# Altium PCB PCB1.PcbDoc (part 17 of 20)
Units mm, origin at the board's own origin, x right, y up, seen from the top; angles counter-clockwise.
Board outline 294.51 x 138.18 mm, 12 copper layers (Top Layer 1 _Signal, L2_GND, L3_Signals, L4_GND, L5_POWER, L6_Signals, L7_GND, L8_Signals, L9_GND, L10_POWER, L11_GND, Bottom Layer_Signals), stack 1.788 mm thick; 1254 components, 836 nets, 5699 pads, 2073 vias.
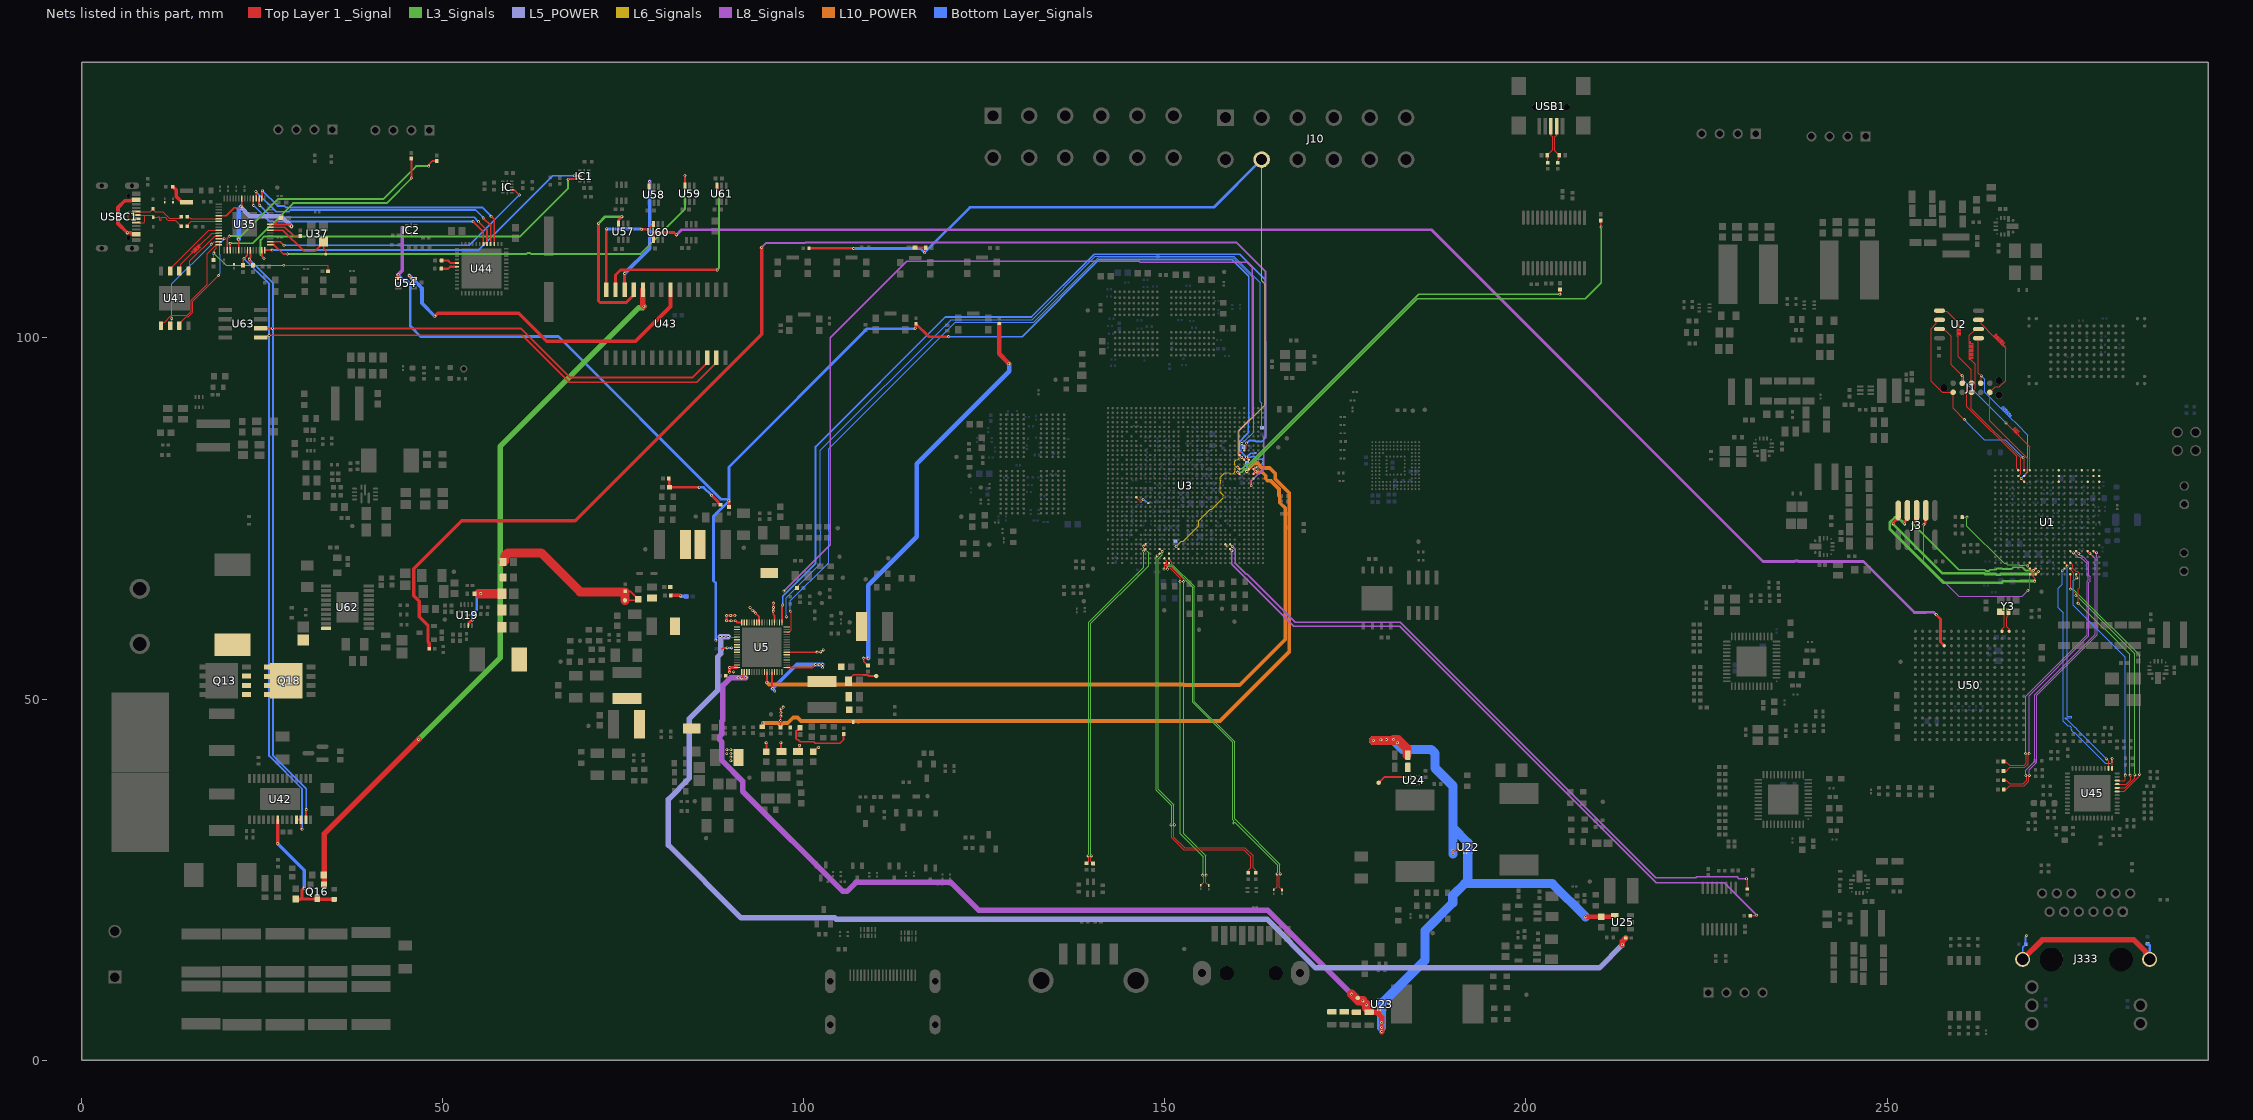
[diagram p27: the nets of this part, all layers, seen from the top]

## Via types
v1: diameter 0.4, hole 0.2, Top Layer 1 _Signal to Bottom Layer_Signals, 2009 vias
v2: diameter 0.508, hole 0.254, Top Layer 1 _Signal to Bottom Layer_Signals, 36 vias
v3: diameter 0.5, hole 0.2, Top Layer 1 _Signal to Bottom Layer_Signals, 12 vias
v4: diameter 1.27, hole 0.711, Top Layer 1 _Signal to Bottom Layer_Signals, 6 vias
v5: diameter 0.3, hole 0.2, Top Layer 1 _Signal to Bottom Layer_Signals, 5 vias
v6: diameter 0.254, hole 0.2, Top Layer 1 _Signal to Bottom Layer_Signals, 3 vias
v7: diameter 0.305, hole 0.2, Top Layer 1 _Signal to Bottom Layer_Signals, 1 vias
v8: diameter 0.254, hole 0.152, Top Layer 1 _Signal to Bottom Layer_Signals, 1 vias

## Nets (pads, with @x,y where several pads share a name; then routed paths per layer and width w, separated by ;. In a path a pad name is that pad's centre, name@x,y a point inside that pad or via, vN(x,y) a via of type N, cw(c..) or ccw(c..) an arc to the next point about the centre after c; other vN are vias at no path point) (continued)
PLDO5: C178.2 C612.1 U3.Y7 U5.65 | length 5
  Top Layer 1 _Signal w0.152: C178.2@96.773,46.044 96.776,46.041 96.788,46.041 96.796,46.049 v1(96.796,47.027) 96.816,47.047 96.816,47.608 v1(96.836,47.627) 96.831,47.632 96.831,48.103 v1(96.826,48.108) 96.838,48.121 96.838,48.622 v1(96.85,48.634) 96.885,48.634 97.128,48.877 v1(97.163,48.877) ; U3.Y7@146.029,77.928 146.356,77.601 v1(146.998,77.601)
  Bottom Layer_Signals w0.152: v1(146.998,77.601) 147.045,77.554 147.254,77.554 147.598,77.21 147.644,77.21 C612.1@147.699,77.155
PMIC_EXT_EN_OUT: R127.2 U5.39 | length 176.9
  Top Layer 1 _Signal w0.127: v1(88.462,58.655) v1(88.943,58.655) v1(89.542,58.655) 89.615,58.655 89.7,58.57 U5.39@90.754,58.57
  Top Layer 1 _Signal w0.762: v1(213.356,15.98) 213.356,16.454 R127.2@213.819,16.917
  L5_POWER w0.762: v1(89.542,58.655) v1(88.943,58.655) v1(88.462,58.655) 88.484,58.633 88.484,56.237 88.11,55.863 88.11,51.227 84.172,47.289 84.172,39.032 81.249,36.109 81.249,29.779 91.337,19.69 104.322,19.69 104.485,19.528 164.134,19.528 170.883,12.779 210.156,12.779 v1(213.356,15.98)
PMIC_FB6: C55.2 R32.1 R33.2 | length 9.4
  Top Layer 1 _Signal w0.381: C55.2@81.315,80.539 81.38,80.474 81.38,79.456 81.377,79.453 R32.1@81.377,79.316 81.379,79.314 85.517,79.314 v1(85.519,79.312) ; v1(87.242,78.219) 88.159,77.302 88.159,77.17 88.414,76.916 R33.2@88.457,76.916
  Bottom Layer_Signals w0.381: v1(85.519,79.312) 86.111,79.312 87.201,78.222 87.239,78.222 v1(87.242,78.219)
PMIC_FB9: C69.2 R35.1 R37.2 U5.66 | length 9.6
  Top Layer 1 _Signal w0.254: R35.1@99.502,46.036 99.502,46.011 99.163,45.672 99.064,45.672 98.941,45.549 98.941,44.534 99.11,44.365 99.226,44.365 99.501,44.091 101.376,44.091 101.585,43.882 105.013,43.882 105.524,44.393 C69.2@105.524,45.164
PMIC_INT_L: R41.1 U3.M30 U5.19 | length 128.7
  Top Layer 1 _Signal w0.203: v1(160.65,83.47) 160.65,83.463 160.979,83.134 U3.M30@160.979,83.128
  L8_Signals w0.203: v1(97.243,64.951) 103.641,71.349 103.641,99.994 114.254,110.607 146.42,110.607 146.523,110.503 161.392,110.503 162.077,109.819 162.077,88.963 161.64,88.526 161.64,88.517 161.414,88.291 161.404,88.291 160.167,87.054 160.167,86.34 160.173,86.335 160.173,86.015 160.167,86.01 160.167,83.952 v1(160.65,83.47)
PMIC_PWR_CTRL1: U3.R32 U5.62 | length 102.1
  Top Layer 1 _Signal w0.254: v1(94.899,52.293) U5.62@94.899,53.725 ; U3.R32@162.279,81.178 162.279,81.188 162.605,81.513 v1(162.605,81.523)
  L10_POWER w0.508: v1(94.899,52.293) 95.182,52.01 152.63,52.01 152.703,51.937 160.358,51.937 166.654,58.233 166.654,76.448 165.911,77.191 165.911,78.046 165.8,78.157 165.8,79.091 164.688,80.203 164.276,80.203 163.961,80.518 163.961,80.929 163.5,81.391 162.737,81.391 v1(162.605,81.523)
PMIC_PWR_CTRL2: R3.1 R20.2 U5.61 | length 110
  Top Layer 1 _Signal w0.381: R20.2@94.227,46.142 94.336,46.251 94.336,46.675 v1(94.34,46.679)
  L10_POWER w0.508: v1(94.34,46.679) 96.384,46.679 96.573,46.49 97.019,46.49 97.208,46.679 97.793,46.679 98.556,47.442 99.147,47.442 99.625,46.963 136.656,46.963 157.625,46.963 167.246,56.584 167.246,78.481 165.307,80.421 165.307,81.185 164.509,81.983 163.43,81.983 163.133,82.28 163.133,82.366 162.817,82.681 162.372,82.681 161.327,81.636 v1(161.327,81.503)
  Bottom Layer_Signals w0.254: v1(161.327,81.503) 161.353,81.529 161.353,82.667 R3.1@161.379,82.693
PMIC_SPI_CLK: R24.2 U5.17 | length 118.8
  Bottom Layer_Signals w0.132: v1(97.596,61.381) 97.596,64.05 102.264,68.719 102.264,72.745 102.367,72.848 102.367,73.137 102.264,73.24 102.264,84.422 120.392,102.55 131.614,102.55 140.37,111.306 159.551,111.306 163.191,107.666 163.191,91.189 163.437,90.943 R24.2@163.437,87.578
PMIC_SPI_CS: U3.K30 U5.18 | length 127.2
  Top Layer 1 _Signal w0.127: U3.K30@160.979,84.428 161.304,84.753 v1(161.304,85.426)
  Top Layer 1 _Signal w0.254: U5.18@96.999,60.615 96.999,62.88 97.096,62.977 v1(97.096,63.017)
  Bottom Layer_Signals w0.254: v1(97.096,63.017) 97.096,64.253 97.383,64.54 97.413,64.54 97.654,64.781 97.654,64.811 101.642,68.799 101.642,72.787 101.607,72.822 101.607,73.163 101.642,73.198 101.642,84.956 119.586,102.901 131.515,102.901 140.197,111.583 160.384,111.583 163.892,108.075 163.892,99.513 163.923,99.482 163.923,91.533 163.952,91.504 163.952,91.164 163.923,91.135 163.923,86.164 163.402,85.642 162.653,85.642 162.481,85.814 161.732,85.814 161.344,85.426 v1(161.304,85.426)
PMIC_SPI_MOSI: R25.2 U3.L29 U5.15 | length 125.1
  Top Layer 1 _Signal w0.152: U5.15@97.644,59.27 97.979,59.27 97.988,59.279 97.988,59.286 98.077,59.375 98.118,59.375 98.237,59.495 98.237,61.976 98.127,62.085 v1(98.127,62.152) ; U3.L29@160.329,83.778 160.333,83.782 160.333,84.019 160.423,84.108 160.462,84.108 160.649,84.295 160.649,84.486 160.659,84.496 160.659,85.375 v1(160.654,85.38)
  Bottom Layer_Signals w0.152: v1(98.127,62.152) 98.127,63.588 103.426,68.886 103.426,72.713 103.549,72.836 103.549,73.134 103.426,73.257 103.426,84.666 120.948,102.187 131.874,102.187 140.767,111.08 159.457,111.08 162.277,108.261 162.277,88.167 162.3,88.144 162.3,87.846 162.277,87.822 162.277,86.967 160.921,85.61 160.885,85.61 v1(160.654,85.38) 160.654,85.313 160.768,85.2 160.768,85 R25.2@160.899,84.868
PMIC_SW1: L1.1 U5.50 U5.51 | length 1.7
  Top Layer 1 _Signal w0.381: v1(89.726,53.719) 89.73,53.723 89.73,54.361 89.739,54.37 U5.51@90.754,54.37
  other v1: 89.909,41.448 89.901,41.95 89.328,42.417 89.901,42.451 89.362,42.973 89.914,42.973 90.292,53.749 89.735,54.367
PMIC_SW2: L5.1 U5.35 U5.36
PMIC_SW3: L11.1 U5.55
PMIC_SW4: L12.1 U5.23
PMIC_SW5: L2.1 U5.45
PMIC_SW6: L3.1 U5.29
PMIC_SW7: L13.1 U5.42
PMIC_SW8: L10.2 U5.6
PMIC_SW9: L7.1 U5.68
PMIC_SW10: L4.2 U5.26
PMIC_VDC: C314.2 R39.1 R40.1 U5.32 | length 2.2
  Top Layer 1 _Signal w0.508: C314.2@81.593,64.346 82.849,64.346 v1(82.913,64.282)
  Bottom Layer_Signals w0.508: v1(82.913,64.282) 82.966,64.229 83.723,64.229 R40.1@83.756,64.197
POWER_SWITCH: Q16.1 R213.2 U43.24 | length 101
  Top Layer 1 _Signal w0.762: Q16.1@33.582,24.314 33.582,31.315 v1(46.667,44.401) ; U43.24@77.728,106.647 77.728,104.511 v1(77.866,104.373)
  L3_Signals w0.762: v1(46.667,44.401) 57.953,55.687 57.953,84.941 77.203,104.191 77.684,104.191 v1(77.866,104.373)
PWM: U1.H1
PWRON_L: C170.2 R181.1 U5.4 | length 56.9
  Top Layer 1 _Signal w0.254: C170.2@108.876,54.63 108.314,55.192 108.314,55.636 v1(108.286,55.664) v1(108.915,55.664)
  Top Layer 1 _Signal w0.635: R181.1@127.043,101.989 127.043,97.793 v1(128.411,96.424)
  Bottom Layer_Signals w0.635: v1(108.915,55.664) 108.915,65.77 115.63,72.485 115.63,82.59 128.439,95.4 128.439,96.396 v1(128.411,96.424)
QSPI.CK: J1.1 U1.P1 U2.6 | length 29.4
  Top Layer 1 _Signal w0.132: U2.6@257.262,102.502 257.019,102.502 256.803,102.286 256.803,102.005 256.096,101.297 256.096,93.968 257.616,92.448 259.141,92.448 J1.1@259.156,92.462 259.156,90.256 v1(260.723,88.688) ; v1(268.849,83.427) 268.849,83.354 268.981,83.222 U1.P1@268.981,81.68
  Bottom Layer_Signals w0.132: v1(260.723,88.688) 260.943,88.468 260.943,88.402 263.458,85.887 266.389,85.887 v1(268.849,83.427)
QSPI.D0: J1.8 U1.R1 U2.5 | length 33
  Top Layer 1 _Signal w0.132: U2.5@257.262,103.772 257.348,103.687 258.29,103.687 259.883,102.093 259.883,101.899 259.883,101.833 260.231,101.833 260.231,101.675 259.688,101.675 259.688,101.518 260.231,101.518 260.231,101.361 259.688,101.361 259.688,101.204 260.231,101.204 260.231,101.047 259.688,101.047 259.688,100.889 260.231,100.889 260.231,100.732 259.688,100.732 259.688,100.575 260.231,100.575 260.231,100.418 259.75,100.418 259.75,100.26 259.883,100.26 259.883,100.048 259.883,97.395 261.696,95.583 J1.8@261.696,93.732 261.051,93.088 261.051,90.5 267.941,83.61 267.941,81.953 268.181,81.713 U1.R1@268.181,81.68
QSPI.D1: J1.3 U1.R2 U2.2 | length 33
  Top Layer 1 _Signal w0.132: U2.2@262.662,101.232 262.275,101.232 261.402,100.36 261.402,99.87 261.402,99.55 261.574,99.55 261.574,99.393 261.377,99.393 261.377,99.236 261.941,99.236 261.941,99.079 261.377,99.079 261.377,98.921 261.941,98.921 261.941,98.764 261.377,98.764 261.377,98.607 261.941,98.607 261.941,98.45 261.377,98.45 261.377,98.293 261.941,98.293 261.941,98.135 261.377,98.135 261.377,97.978 261.941,97.978 261.941,97.821 261.377,97.821 261.377,97.664 261.941,97.664 261.941,97.506 261.377,97.506 261.377,97.349 261.941,97.349 261.941,97.192 261.377,97.192 261.377,97.035 261.558,97.035 261.623,96.969 262.239,96.353 262.239,93.006 J1.3@261.696,92.462 261.696,90.184 268.496,83.384 268.496,81.195 U1.R2@268.181,80.88
QSPI.D2: J1.5 U1.P2 U2.3 | length 33
  Top Layer 1 _Signal w0.132: U2.3@262.662,102.502 262.855,102.502 263.071,102.286 263.071,101.934 264.739,100.266 264.785,100.22 265.11,100.544 265.221,100.433 264.879,100.091 264.99,99.98 265.332,100.322 265.443,100.211 265.101,99.868 265.212,99.757 265.554,100.099 265.666,99.988 265.323,99.646 265.434,99.535 265.777,99.877 265.888,99.766 265.546,99.424 265.657,99.313 265.999,99.655 266.11,99.544 265.768,99.201 265.879,99.09 266.221,99.432 266.333,99.321 265.99,98.979 266.102,98.868 266.224,98.991 266.336,98.88 266.231,98.775 266.408,98.597 266.408,98.473 266.408,94.097 265.527,93.216 264.989,93.216 J1.5@264.236,92.462 264.236,88.535 269.497,83.274 269.497,81.964 269.419,81.887 269.419,81.318 U1.P2@268.981,80.88
QSPI.D3: J1.9 U1.N1 U2.7 | length 29.5
  Top Layer 1 _Signal w0.132: U2.7@257.262,101.232 257.864,101.232 258.086,101.009 258.146,101.009 258.901,100.255 258.901,96.281 v1(260.389,94.793) 260.407,94.775 260.407,93.75 J1.9@260.426,93.732 ; v1(266.473,88.229) 267.34,87.362 267.387,87.316 267.729,87.658 267.84,87.547 267.48,87.187 267.591,87.075 267.951,87.436 268.062,87.324 267.702,86.964 267.813,86.853 268.173,87.213 268.285,87.102 267.924,86.742 268.036,86.631 268.113,86.708 268.225,86.597 268.165,86.538 269.353,85.349 269.781,84.921 U1.N1@269.781,81.68
  Bottom Layer_Signals w0.132: v1(260.389,94.793) 260.462,94.793 260.55,94.705 260.55,94.107 266.428,88.229 v1(266.473,88.229)
QSPI.nCS: J1.7 U1.P3 U2.1 | length 29.5
  Top Layer 1 _Signal w0.132: U2.1@262.662,99.962 262.662,95.139 v1(263.058,94.742) 263.012,94.696 263.012,93.779 J1.7@262.966,93.732 ; v1(268.585,80.557) 268.585,80.476 U1.P3@268.981,80.08
  Bottom Layer_Signals w0.132: v1(263.058,94.742) 263.531,94.27 263.531,92.513 265.753,90.29 265.8,90.244 266.101,90.545 266.213,90.434 265.893,90.115 266.004,90.003 266.324,90.323 266.435,90.212 266.116,89.892 266.227,89.781 266.546,90.101 266.657,89.989 266.338,89.67 266.449,89.559 266.768,89.878 266.88,89.767 266.56,89.448 266.671,89.336 266.991,89.656 267.102,89.545 266.783,89.225 266.894,89.114 267.15,89.37 267.261,89.259 267.023,89.021 268.014,88.03 269.497,86.547 269.497,81.469 v1(268.585,80.557)
QSPI_CLK: U35.56 U41.6 | length 12.1
  Top Layer 1 _Signal w0.132: U41.6@13.524,109.266 13.758,109.5 13.758,110.215 15.327,111.783 15.373,111.829 15.208,111.995 15.319,112.106 15.634,111.791 15.745,111.902 15.43,112.217 15.541,112.328 15.857,112.013 15.968,112.124 15.652,112.44 15.764,112.551 16.079,112.235 16.19,112.346 15.875,112.662 15.986,112.773 16.301,112.458 16.412,112.569 16.097,112.884 16.208,112.995 16.374,112.83 16.53,112.986 18.071,114.528 U35.56@18.994,114.528
QSPI_SD0: U35.57 U41.5 | length 7.3
  Top Layer 1 _Signal w0.132: U41.5@14.794,109.266 14.991,109.463 14.991,110.669 18.415,114.094 18.96,114.094 U35.57@18.994,114.128 U35.57@18.657,114.128
QSPI_SD1: U35.59 U41.2 | length 14.8
  Top Layer 1 _Signal w0.132: U41.2@12.254,101.666 12.484,101.896 v1(12.484,102.7) ; v1(17.996,112.982) 18.342,113.328 U35.59@18.994,113.328
  Bottom Layer_Signals w0.132: v1(12.484,102.7) 12.484,107.47 v1(17.996,112.982)
QSPI_SD2: U35.58 U41.3 | length 15.6
  Top Layer 1 _Signal w0.132: U41.3@13.524,101.666 13.524,101.966 14.459,102.901 14.747,102.901 15.424,103.579 15.424,105.1 v1(18.953,108.629) ; U35.58@18.994,113.728 18.997,113.731 19.738,113.731 v1(19.741,113.733)
  Bottom Layer_Signals w0.132: v1(18.953,108.629) 18.953,108.701 19.195,108.944 19.195,111.488 19.15,111.533 19.15,113.095 19.741,113.686 v1(19.741,113.733)
QSPI_SD3: U35.55 U41.7 | length 9.3
  Top Layer 1 _Signal w0.132: U41.7@12.254,109.266 12.254,109.566 17.616,114.928 U35.55@18.994,114.928
QSPI_SS: R203.1 R204.2 U35.60 U41.1 | length 35.9
  Top Layer 1 _Signal w0.132: U41.1@10.984,101.666 10.984,101.966 11.218,102.2 11.482,102.2 12.403,103.121 14.606,103.121 15.189,103.704 15.189,105.213 17.388,107.412 17.388,111.659 U35.60@18.623,112.893 ; R203.1@18.257,110.818 18.327,110.889 v1(18.327,111.737) 18.359,111.769 18.359,112.135 18.623,112.398 U35.60@18.623,112.893 ; U35.60@18.994,112.928 18.657,112.928 U35.60@18.623,112.893 ; v1(27.994,110.059) 34.141,110.059 R204.2@34.141,109.251
  L3_Signals w0.132: v1(18.327,111.737) 20.006,110.059 v1(27.994,110.059)
  Bottom Layer_Signals w0.132: 18.117,111.649 v1@18.167,111.649 ; v1@18.255,111.737 v1(18.327,111.737)
RD0_VS_N: C634.2 U1.B15 | length 40.1
  Top Layer 1 _Signal w0.161: C634.2@266.148,37.482 266.489,37.482 266.966,37.959 268.984,37.959 269.631,38.606 269.631,39.378 269.674,39.422 v1(269.716,39.422) ; U1.B15@278.581,70.48 278.627,70.48 278.86,70.247 v1(279.013,70.247)
  L8_Signals w0.115: v1(269.716,39.422) 269.716,40.235 270.732,41.251 270.732,50.505 279.113,58.886 279.113,69.526 279.013,69.626 v1(279.013,70.247)
RD0_VS_P: C633.2 U1.C15 | length 39.8
  Top Layer 1 _Signal w0.161: C633.2@266.148,38.75 266.489,38.75 266.966,38.273 268.854,38.273 269.317,38.736 269.317,39.378 269.274,39.422 v1(269.232,39.422) ; U1.C15@277.781,70.48 v1(278.09,70.171)
  L8_Signals w0.115: v1(269.232,39.422) 269.232,40.129 270.464,41.361 270.464,50.616 278.845,58.997 278.845,69.416 v1(278.09,70.171)
REFCLK_N: U50.C1 Y3.5 | length 2.9
  Top Layer 1 _Signal w0.161: Y3.5@266.809,62.079 266.809,61.573 266.576,61.34 266.576,60.021 266.919,59.678 U50.C1@266.919,59.379
REFCLK_P: U50.D1 Y3.4 | length 3
  Top Layer 1 _Signal w0.161: Y3.4@265.759,62.079 266.262,61.576 266.262,60.021 265.919,59.678 U50.D1@265.919,59.379
RESET_L: C30.1 IC2.8 R9.2 R172.1 R179.1 U3.M31 U5.40 U54.4 | length 213.2
  Top Layer 1 _Signal w0.203: v1@161.273,83.445 v1@161.337,83.509 ; v1(161.304,83.476) 161.304,83.464 161.629,83.139 U3.M31@161.629,83.128
  Top Layer 1 _Signal w0.381: U54.4@43.815,108.209 43.818,108.212 43.818,108.754 v1(43.821,108.757) ; v1(44.407,115.32) 44.411,115.316 45.019,115.316 IC2.8@45.042,115.293 ; v1(89.633,77.427) 89.633,77.422 89.648,77.407 R172.1@89.648,76.602 ; v1(115.406,101.312) 115.406,101.317 115.492,101.403 115.492,101.901 115.534,101.943 R179.1@115.538,101.943 115.542,101.943 117.311,100.174 v1(120.066,100.174)
  L8_Signals w0.508: v1(43.821,108.757) 44.407,109.343 v1(44.407,115.32)
  Bottom Layer_Signals w0.203: v1(120.066,100.174) 130.23,100.174 140.853,110.797 156.392,110.797 156.413,110.819 159.349,110.819 161.64,108.528 161.64,88.517 161.555,88.431 161.555,86.863 160.712,86.02 160.712,85.983 160.269,85.54 160.269,85.22 160.349,85.141 160.349,84.431 v1(161.304,83.476) ; C30.1@162.538,84.077 162.519,84.058 161.862,84.058 161.304,83.5 v1(161.304,83.476) ; R9.2@163.589,83.224 163.58,83.233 162.753,83.233 162.447,83.539 161.934,83.539 161.871,83.476 v1(161.304,83.476)
  Bottom Layer_Signals w0.381: v1(43.821,108.757) 44.442,108.136 44.885,108.136 45.502,107.519 45.502,101.629 46.922,100.21 66.009,100.21 88.563,77.656 89.41,77.656 ; v1(87.819,58.152) 87.819,66.065 87.515,66.37 87.515,75.308 v1(89.633,77.427) v1@89.633,77.432 ; 89.41,77.655 v1@89.633,77.432 ; v1(115.406,101.312) 115.379,101.285 108.784,101.285 89.633,82.134 v1@89.633,77.432
RESET_L_: U43.21 U54.3 | length 46.6
  Top Layer 1 _Signal w0.254: v1(45.37,108.634) 45.37,108.605 45.765,108.209 U54.3@46.015,108.209
  Top Layer 1 _Signal w0.508: v1(48.911,103.016) 49.324,103.43 60.523,103.43 64.418,99.535 76.712,99.535 81.538,104.36 U43.21@81.538,106.647
  Bottom Layer_Signals w0.508: v1(45.37,108.634) 47.14,106.864 47.14,104.786 v1(48.911,103.016)
RK_RX: R306.2 U44.18 | length 2.3
  Top Layer 1 _Signal w0.3: R306.2@49.823,109.582 50.755,109.582 51.032,109.859 U44.18@51.989,109.859
RK_TX: R305.2 U44.17 | length 2.3
  Top Layer 1 _Signal w0.3: R305.2@49.84,110.717 50.743,110.717 51.101,110.359 U44.17@51.989,110.359
RP_1V1: C451.2 C561.1 C562.2 C565.2 C566.2 L25.1 U35.6 U35.23 U35.39 U35.50 | length 26.6
  Top Layer 1 _Signal w0.254: U35.50@18.994,116.928 20.014,116.928 21.108,118.021 21.882,118.021 22.024,118.163 v1(22.063,118.163) 22.063,118.202 22.169,118.309 U35.39@22.169,119.303 ; v1(21.75,113.673) 21.76,113.663 21.76,112.162 U35.6@21.769,112.153 ; U35.23@26.144,115.728 28.799,115.728 v1(29.067,115.46) ; 26.686,115.755 27.542,116.61 C451.2@27.592,116.61
  Top Layer 1 _Signal w0.508: C561.1@12.631,120.933 13.127,120.438 13.127,119.551 13.891,118.787 L25.1@14.491,118.787
  L5_POWER w0.6: v1(22.063,118.163) 22.063,118.1 23.332,116.831 27.695,116.831 v1(29.067,115.46)
  Bottom Layer_Signals w0.6: v1(21.75,113.673) 21.75,117.849 v1(22.063,118.163)
RP_COMA_VSC: U43.27 U61.3 | length 28.3
  Top Layer 1 _Signal w0.254: U61.3@87.964,121.049 88.037,120.976 88.037,120.324 v1(88.24,120.12)
  Top Layer 1 _Signal w0.381: U43.27@73.918,106.647 73.918,108.727 74.614,109.423 74.94,109.423 74.969,109.452 87.953,109.452 87.999,109.407 v1(88.015,109.407)
  L3_Signals w0.254: v1(88.015,109.407) 88.015,109.446 88.24,109.671 v1(88.24,120.12)
RP_D_N: D5.2 R198.1 USBC1.A7 USBC1.B7 | length 10.2
  Top Layer 1 _Signal w0.161: USBC1.A7@7.558,116.505 7.504,116.452 6.553,116.452 6.458,116.546 6.458,117.396 6.553,117.49 7.543,117.49 USBC1.B7@7.558,117.505 7.573,117.49 9.52,117.49 D5.2@9.875,117.845 ; R198.1@13.807,116.782 13.807,116.78 13.653,116.626 13.584,116.626 13.559,116.602 12.11,116.602 11.221,117.49 10.798,117.49 10.231,117.49 D5.2@9.875,117.845 ; D5.2@9.875,117.845 D5.2@9.875,117.885 D5.2@9.875,117.845
RP_D_P: D6.1 R199.1 USBC1.A6 USBC1.B6 | length 10.2
  Top Layer 1 _Signal w0.161: USBC1.B6@7.558,116.005 7.588,115.975 8.675,115.975 8.77,116.069 8.77,116.975 ; USBC1.A6@7.558,117.005 7.588,116.975 8.77,116.975 ; R199.1@13.817,115.455 R199.1@13.817,115.455 13.664,115.61 13.662,115.61 12.984,116.288 11.98,116.288 11.888,116.38 11.568,116.699 11.343,116.699 11.317,116.726 11.183,116.726 11.01,116.726 11.01,116.318 10.823,116.318 10.823,116.791 10.637,116.791 10.637,116.726 10.556,116.726 9.93,116.726 D6.1@9.918,116.715 9.918,116.804 9.895,116.804 9.895,117 9.708,117 9.708,116.975 9.628,116.975 8.77,116.975
RP_IN: C563.1 U35.21 U37.1 | length 11.1
  Top Layer 1 _Signal w0.203: U35.21@26.144,114.928 27.878,114.928 30.799,112.007 32.278,112.007 33.497,113.226 U37.1@33.497,113.326 33.497,112.321 33.779,112.039 33.779,111.632 33.814,111.597 C563.1@33.814,111.574
RP_MDC_VSC: U35.16 U59.3 | length 66.7
  Top Layer 1 _Signal w0.254: U35.16@26.144,112.928 26.634,112.928 27.939,111.622 v1(28.499,111.622) ; U59.3@83.535,121.079 v1(83.535,122.488)
  L3_Signals w0.254: v1(28.499,111.622) 61.592,111.622 61.733,111.763 62.073,111.763 62.215,111.622 77.371,111.622 80.532,114.782 80.532,114.828 83.535,117.831 v1(83.535,122.488)
RP_MDIO_0: IC1.10 U35.14 | length 52.5
  Top Layer 1 _Signal w0.254: U35.14@24.969,112.153 24.969,111.302 v1(25.257,111.014) ; v1(67.373,121.952) 67.413,121.952 67.479,122.018 IC1.10@69.002,122.018
  L3_Signals w0.254: v1(25.257,111.014) 24.777,111.494 24.777,113.554 25.273,114.05 60.711,114.05 67.373,120.713 v1(67.373,121.952)
RP_MDIO_1: IC1.9 U35.15 | length 47.9
  Top Layer 1 _Signal w0.254: U35.15@25.369,112.153 v1(26.391,112.153) ; v1(68.246,122.45) 68.82,122.45 68.825,122.445 68.975,122.445 IC1.9@69.002,122.418
  Bottom Layer_Signals w0.254: v1(26.391,112.153) 54.924,112.153 65.221,122.45 v1(68.246,122.45)
RP_MDIO_VSC: IC.8 U35.17 | length 38.9
  Top Layer 1 _Signal w0.254: U35.17@26.144,113.328 27.536,113.328 v1(28.024,112.839) ; IC.8@59.54,120.492 59.567,120.465 59.942,120.465 v1(60.618,119.789)
  Bottom Layer_Signals w0.254: v1(28.024,112.839) 53.668,112.839 v1(60.618,119.789)
RP_OUT: R200.2 U35.22 | length 4.6
  Top Layer 1 _Signal w0.203: U35.22@26.144,115.328 28.145,115.328 29.351,114.121 R200.2@30.27,114.121
RP_RST_DP0: U43.25 U57.3 | length 21.6
  Top Layer 1 _Signal w0.381: v1(71.58,115.871) 71.58,105.136 71.803,104.913 75.424,104.913 76.458,105.947 U43.25@76.458,106.647 ; U57.3@74.358,115.799 74.367,115.809 74.367,116.328 74.804,116.764 v1(74.804,116.784)
  L3_Signals w0.381: v1(71.58,115.871) 72.493,116.784 v1(74.804,116.784)
RP_RST_DP1: U43.26 U58.3 | length 17.4
  Top Layer 1 _Signal w0.254: U58.3@78.594,120.939 78.636,120.981 78.636,121.624 v1(78.664,121.652)
  Top Layer 1 _Signal w0.381: U43.26@75.188,106.647 v1@75.188,108.903
  Top Layer 1 _Signal w0.508: v1@75.188,108.903 v1(75.188,108.923)
  Bottom Layer_Signals w0.508: v1(75.188,108.923) 78.664,112.399 78.664,113.886 78.908,114.13 78.908,114.576 78.664,114.82 v1(78.664,121.652)
RP_RST_VSC: U43.28 U60.3 | length 15.5
  Top Layer 1 _Signal w0.381: U43.28@72.648,106.647 72.648,115.03 72.711,115.093 v1(72.711,115.098) ; v1(77.526,115.048) 78.456,115.048 78.914,115.506 79.164,115.506 79.173,115.516 U60.3@79.173,115.766
  Bottom Layer_Signals w0.381: v1(72.711,115.098) 74.879,115.098 74.973,115.192 75.366,115.192 75.459,115.098 77.471,115.098 77.521,115.048 v1(77.526,115.048)
RP_SCL: R194.1 U35.10 U42.13 U43.12 U63.6 | length 149.4
  Top Layer 1 _Signal w0.254: U35.10@23.369,112.153 23.368,112.151 23.368,111.121 23.21,110.963 v1(23.21,110.923) 23.238,110.895 23.238,110.589 23.745,110.082 R194.1@23.745,110.075 ; U63.6@24.808,101.325 v1(26.436,101.325) 60.803,101.325 67.596,94.532 84.603,94.532 86.618,96.547 U43.12@86.618,97.247 ; U42.13@31.054,33.296 31.054,34.633 v1(31.107,34.686)
  Bottom Layer_Signals w0.254: v1(23.21,110.923) 26.488,107.646 26.488,42.211 31.107,37.591 v1(31.107,34.686)
RP_SDA: R195.1 U35.9 U42.11 U42.12 U43.13 U63.5 | length 154.8
  Top Layer 1 _Signal w0.254: R195.1@22.373,110.073 22.373,110.839 22.487,110.953 v1(22.487,110.993) 22.942,111.448 22.942,112.126 U35.9@22.969,112.153 ; U63.5@24.808,100.055 25.458,100.055 25.631,100.228 25.818,100.228 25.93,100.339 v1(25.969,100.339) ; v1@25.944,100.365 61.004,100.365 67.501,93.868 85.209,93.868 87.888,96.547 U43.13@87.888,97.247 ; U42.11@29.754,33.296 30.332,33.296 30.405,33.223 U42.12@30.405,32.951 ; U42.12@30.405,33.296 U42.12@30.405,32.951 ; v1(30.529,31.966) 30.529,32.005 30.405,32.13 U42.12@30.405,32.951
  Bottom Layer_Signals w0.254: v1(22.487,110.993) 25.969,107.51 v1(25.969,100.339) 25.954,100.324 25.954,42.116 30.529,37.541 v1(30.529,31.966)
RP_VBUS: USBC1.A4_B9 USBC1.B4_A9 | length 8.3
  Top Layer 1 _Signal w0.508: v1(6.323,114.549) 5.043,115.829 5.043,118.058 5.977,118.992 6.868,118.992 6.985,119.109 7.512,119.109 USBC1.A4_B9@7.558,119.155 ; v1@6.349,114.575 6.781,114.575 6.97,114.386 7.527,114.386 USBC1.B4_A9@7.558,114.355
RPD_N: R198.2 U35.51 | length 4.5
  Top Layer 1 _Signal w0.161: R198.2@14.611,116.782 14.611,116.78 14.765,116.626 15.026,116.626 15.168,116.484 18.433,116.484 18.476,116.528 U35.51@18.994,116.528
RPD_P: R199.2 U35.52 | length 4.8
  Top Layer 1 _Signal w0.161: R199.2@14.621,115.455 14.775,115.608 14.775,115.753 15.193,116.171 18.433,116.171 18.476,116.128 U35.52@18.994,116.128
RST_VSC: U50.M3 U60.4 | length 205.9
  Top Layer 1 _Signal w0.381: U60.4@79.173,113.566 79.173,114.381 79.396,114.604 82.029,114.604 v1(82.369,114.265) ; v1(256.802,61.688) 257.411,61.078 257.411,57.902 257.919,57.394 U50.M3@257.919,57.379
  L8_Signals w0.381: v1(82.369,114.265) 83.083,114.979 186.92,114.979 232.848,69.05 237.204,69.05 237.281,69.128 237.674,69.128 237.752,69.05 246.725,69.05 253.778,61.997 255.369,61.997 255.378,62.006 256.483,62.006 v1(256.802,61.688)
SARADC_VIN1_KEY/RECOVERY: J10.8 R128.1 R177.1 R178.2 U3.AL16 U16.1 | length 132.4
  Top Layer 1 _Signal w0.132: v1(151.554,71.126) 151.554,71.103 U3.AL16@151.879,70.778
  Top Layer 1 _Signal w0.254: R178.2@115.41,112.503 115.414,112.506 116.895,112.506 U16.1@116.898,112.51 116.775,112.387 116.775,111.901 116.74,111.865 v1(116.74,111.825)
  Top Layer 1 _Signal w0.381: R177.1@100.72,112.425 106.866,112.425 v1(106.91,112.381)
  L6_Signals w0.106: v1(151.554,71.126) 152.274,71.846 152.556,71.846 154.671,73.96 154.671,74.718 156.262,76.309 156.498,76.309 158.089,77.9 158.089,78.206 157.674,78.62 157.674,79.936 157.715,79.976 157.715,80.255 157.674,80.295 157.674,80.706 158.283,81.315 158.918,81.315 159.045,81.189 159.494,81.189 159.696,81.391 159.696,81.515 159.743,81.562 159.743,82.265 159.649,82.359 159.649,82.901 159.864,83.116 160.099,83.116 160.313,83.33 160.313,87.2 163.878,90.765 163.878,107.41 163.395,107.894 J10.8@163.395,124.704
  Bottom Layer_Signals w0.132: R128.1@151.489,71.847 151.448,71.806 151.554,71.7 v1(151.554,71.126)
  Bottom Layer_Signals w0.381: v1(106.91,112.381) 116.184,112.381 v1(116.74,111.825) 122.997,118.083 156.774,118.083 J10.8@163.395,124.704
SDMMC_DET_L: U3.P31
SE.RC0: U1.H3
SGPIO.CK: U1.A2
SGPIO.DI: U1.B2
SGPIO.DO: U1.B1
SGPIO.LD: U1.A3
SHIELD_GND_MNG: C380.1 J333.0 R399.1 | length 26
  Top Layer 1 _Signal w0.762: J333.0@268.786,13.94 271.495,16.649 284.187,16.649 285.848,14.988 285.848,14.815 286.366,14.297 J333.0@286.366,13.94
  Bottom Layer_Signals w0.254: J333.0@268.786,13.94 268.786,15.61 269.189,16.013 R399.1@269.189,16.03 269.189,17.089 269.337,17.237 v1(269.337,17.276)
  Bottom Layer_Signals w0.381: C380.1@286.075,16.127 286.091,16.127 286.366,15.852 J333.0@286.366,13.94
SPI0_CsN: U35.33 U44.5 | length 35.8
  Top Layer 1 _Signal w0.254: U35.33@24.569,119.303 24.569,118.501 24.674,118.396 v1(24.674,118.357) ; v1(54.96,116.109) 56.139,114.929 U44.5@56.139,113.009
  Bottom Layer_Signals w0.254: v1(24.674,118.357) 26.313,116.719 54.342,116.719 54.952,116.109 v1(54.96,116.109)
SPI0_RX: U35.32 U44.3 | length 38.3
  Top Layer 1 _Signal w0.254: U35.32@24.969,119.303 24.969,120.273 25.044,120.348 v1(25.044,120.387) ; v1(56.707,116.85) 57.139,116.417 U44.3@57.139,113.009
  Bottom Layer_Signals w0.254: v1(25.044,120.387) 27.145,118.286 28.073,118.286 28.282,118.077 55.479,118.077 v1(56.707,116.85)
SPI0_SCK: U35.34 U44.4 | length 38.3
  Top Layer 1 _Signal w0.203: v1(24.138,120.275) 24.168,120.245 24.168,119.304 U35.34@24.169,119.303 ; v1(55.614,116.603) 56.639,115.578 U44.4@56.639,113.009
  Bottom Layer_Signals w0.254: v1(24.138,120.275) 26.948,117.465 28.673,117.465 28.926,117.718 54.569,117.718 55.516,116.77 55.516,116.755 55.614,116.656 v1(55.614,116.603)
SPI0_TX: U35.35 U44.6 | length 36
  Top Layer 1 _Signal w0.203: U35.35@23.769,119.303 23.769,118.447 23.826,118.391 v1(23.826,118.338) ; v1(54.204,116.108) 55.639,114.672 U44.6@55.639,113.009
  Bottom Layer_Signals w0.254: v1(23.826,118.338) 26.055,116.108 v1(54.204,116.108)
SW_LM: C219.1 L29.1 Q13.1 Q13.2 Q13.3 Q18.5 Q18.6 Q18.7 Q18.8 U62.20
SYS4V0_MODE_L: R89.2 U3.T32 | length 189.3
  Top Layer 1 _Signal w0.132: v1(161.957,79.533) 161.939,79.55 161.939,80.451 162.016,80.528 U3.T32@162.279,80.528
  Top Layer 1 _Signal w0.457: R89.2@48.132,56.972 R89.2@48.15,56.972 48.15,57.707 47.973,57.884 47.973,60.173 46.741,61.405 46.741,63.521 45.994,64.268 45.994,68.055 52.613,74.674 68.327,74.674 94.182,100.529 94.182,112.518 v1(94.153,112.547)
  L8_Signals w0.254: v1@93.999,112.439 v1@94.153,112.439 ; v1(94.153,112.547) 94.746,113.141 100.149,113.141 100.207,113.199 159.939,113.199 163.952,109.186 163.952,86.452 163.683,86.183 163.683,81.912 161.957,80.185 v1(161.957,79.533)
TACH: U1.H2
TCK: J3.2 U1.M19 | length 25.9
  Top Layer 1 _Signal w0.254: U1.M19@270.581,67.28 v1(270.97,67.669)
  Top Layer 1 _Signal w0.381: v1(250.85,74.258) 250.85,74.386 251.551,75.087 J3.2@251.551,76.112
  L3_Signals w0.381: v1(250.85,74.258) 257.699,67.408 263.466,67.408 263.56,67.314 265.099,67.314 265.205,67.207 265.649,67.207 265.755,67.314 270.61,67.314 270.965,67.669 v1(270.97,67.669)
TD0_VS_N: C631.2 U1.E15 | length 37.8
  Top Layer 1 _Signal w0.161: C631.2@266.142,40.018 266.482,40.018 266.983,40.518 269.1,40.518 269.579,40.997 269.579,42.35 v1(269.664,42.435) ; U1.E15@276.181,70.48 276.203,70.48 v1@276.48,70.203
  L8_Signals w0.115: v1(269.664,42.435) 269.664,50.465 277.96,58.762 277.96,66.175 278.119,66.334 278.119,67.009 277.96,67.169 277.96,68.875 277.154,69.682 277.09,69.682 276.895,69.876 276.695,69.876 276.61,69.961 276.61,70.114 v1(276.555,70.168)
TD0_VS_P: C630.2 U1.F15 | length 37.8
  Top Layer 1 _Signal w0.161: C630.2@266.126,41.332 266.466,41.332 266.967,40.832 268.97,40.832 269.265,41.127 269.265,42.35 v1(269.18,42.435) ; U1.F15@275.381,70.48 275.427,70.48 275.619,70.288 275.75,70.288 v1(275.796,70.242)
  L8_Signals w0.115: v1(269.18,42.435) 269.18,50.36 277.693,58.873 277.693,66.285 277.852,66.445 277.852,66.899 277.693,67.058 277.693,68.765 277.043,69.414 276.979,69.414 276.785,69.609 276.49,69.609 275.856,70.242 v1(275.796,70.242)
TDI: J3.4 U1.N18 | length 31
  Top Layer 1 _Signal w0.132: U1.N18@269.781,68.08 269.819,68.042 269.819,67.727 270.266,67.28 270.266,66.939 270.457,66.748 v1(270.457,66.334)
  Top Layer 1 _Signal w0.381: v1(252.447,74.241) 252.447,74.568 252.821,74.942 J3.4@252.821,76.112
  L3_Signals w0.381: v1(252.447,74.241) 251.528,75.16 251.082,75.16 250.375,74.454 250.375,73.531 257.813,66.094 265.838,66.094 266.069,66.324 268.423,66.324 268.433,66.334 v1(270.457,66.334)
TDO: J3.6 U1.M18 | length 22.4
  Top Layer 1 _Signal w0.254: v1(270.268,67.788) 270.56,68.08 U1.M18@270.581,68.08
  Top Layer 1 _Signal w0.381: v1(253.534,74.274) 253.534,74.385 254.091,74.942 J3.6@254.091,76.112
  L3_Signals w0.254: v1(253.534,74.274) 259.901,67.908 263.534,67.908 263.698,67.743 264.125,67.743 264.29,67.908 265.047,67.908 265.232,68.093 265.917,68.093 266.007,68.002 267.246,68.002 267.49,68.246 268.729,68.246 269.187,67.788 v1(270.268,67.788)
TMS: J3.8 U1.N19 | length 26.3
  Top Layer 1 _Signal w0.136: v1(269.505,65.006) 269.781,65.282 U1.N19@269.781,67.28
  Top Layer 1 _Signal w0.381: v1(255.099,74.159) 255.288,74.348 255.288,76.039 J3.8@255.361,76.112
  L8_Signals w0.136: v1(255.099,74.159) 255.099,69.04 259.906,64.233 268.732,64.233 v1(269.505,65.006)
TRSTn: R5.1 U1.N17 | length 13.3
  Top Layer 1 _Signal w0.132: v1@269.452,68.415 v1(269.481,68.415) 269.467,68.429 269.467,68.566 U1.N17@269.781,68.88
  Top Layer 1 _Signal w0.161: R5.1@260.42,75.196 v1(261.07,75.196)
  L3_Signals w0.161: v1(261.07,75.196) 261.07,73.917 266.21,68.777 266.485,68.777 266.643,68.62 268.286,68.62 268.368,68.538 268.987,68.538 269.069,68.62 269.267,68.62 269.472,68.415 v1(269.481,68.415)
TSADC_SHUT_H: R9.1 U3.P32 | length 1.7
  Top Layer 1 _Signal w0.254: U3.P32@162.279,81.828 v1(162.595,82.143)
  Bottom Layer_Signals w0.203: v1(162.595,82.143) 162.632,82.181 163.099,82.181 163.589,82.67 R9.1@163.589,82.716
TX_CLK: U1.G18 U45.25 | length 33.1
  Top Layer 1 _Signal w0.132: v1(274.261,67.76) U1.G18@274.581,68.08 ; v1(281.163,41.748) 281.174,41.737 U45.25@281.174,40.403
  Bottom Layer_Signals w0.132: v1(274.261,67.76) 274.261,65.905 273.702,65.345 273.702,62.654 274.4,61.957 274.4,46.939 275.014,46.325 275.318,46.325 275.523,46.12 275.523,45.816 275.602,45.737 275.602,45.614 275.806,45.409 275.93,45.409 280.222,41.117 281.008,41.117 281.163,41.272 v1(281.163,41.748)
TX_ER: U1.G17 U45.26 | length 32.8
  Top Layer 1 _Signal w0.132: U1.G17@274.581,68.88 274.927,68.534 v1(274.927,68.412) ; v1(280.373,41.714) 280.674,41.412 U45.26@280.674,40.403
  Bottom Layer_Signals w0.132: v1(274.927,68.412) 274.927,49.41 274.927,47.586 275.582,47.586 275.582,47.429 274.709,47.429 274.709,47.272 274.927,47.272 274.927,47.206 274.927,47.16 275.978,46.108 276.096,46.108 276.301,45.903 276.301,45.785 v1(280.373,41.714)
TXD0: U1.F19 U45.19 | length 36.1
  Top Layer 1 _Signal w0.132: U1.F19@275.381,67.28 275.406,67.255 275.406,65.248 v1(275.431,65.223) ; U45.19@281.874,37.203 282.856,37.203 284.95,39.297 284.95,39.551 v1(284.973,39.574)
  L3_Signals w0.113: v1(275.431,65.223) 275.761,65.223 276.461,64.524 276.499,64.524 284.973,56.05 v1(284.973,39.574)
TXD1: U1.F18 U45.20 | length 35.8
  Top Layer 1 _Signal w0.132: U1.F18@275.381,68.08 275.419,68.042 275.419,67.881 275.866,67.433 275.866,67.15 275.884,67.132 275.884,64.913 276.151,64.646 v1(276.151,64.328) ; U45.20@281.874,37.703 283,37.703 284.317,39.02 v1(284.317,39.5)
  L3_Signals w0.113: v1(276.151,64.328) 276.229,64.328 276.337,64.22 276.341,64.22 284.317,56.244 v1(284.317,39.5)
TXD2: U1.F17 U45.21 | length 36
  Top Layer 1 _Signal w0.132: U1.F17@275.381,68.88 275.735,68.526 275.735,68.081 276.155,67.661 276.334,67.661 276.666,67.328 276.666,65.436 276.501,65.271 276.501,63.306 v1(276.463,63.267) ; U45.21@281.874,38.203 283.114,38.203 283.744,38.834 283.744,39.25 283.722,39.272 283.722,39.41 v1(283.67,39.461)
  L3_Signals w0.113: v1(276.463,63.267) 280.01,59.72 280.127,59.72 283.619,56.228 283.619,39.512 v1(283.67,39.461)
TXD3: U1.E19 U45.22 | length 32.9
  Top Layer 1 _Signal w0.132: U1.E19@276.181,67.28 276.203,67.258 276.203,66.917 276.284,66.836 v1(276.284,66.763) ; U45.22@281.874,38.703 282.842,38.703 282.992,38.853 v1(282.992,39.467)
  Bottom Layer_Signals w0.132: v1(276.284,66.763) 276.212,66.763 275.974,66.525 275.916,66.525 275.802,66.411 275.802,62.963 282.992,55.773 v1(282.992,39.467)
TYPEC0_OTG_D_N: R93.1 U3.AM12 | length 54.9
  Top Layer 1 _Signal w0.131: v1(148.937,69.815) 148.952,69.815 149.265,70.128 U3.AM12@149.279,70.128 ; v1(150.851,32.577) 150.938,32.489 150.938,30.759 152.595,29.101 160.955,29.101 161.912,28.145 161.912,26.647 161.547,26.282 R93.1@161.547,25.966
  L3_Signals w0.118: v1(148.937,69.815) 148.937,69.739 148.841,69.643 148.841,69.613 148.795,69.567 148.795,37.37 150.93,35.235 150.93,32.787 150.904,32.761 150.904,32.631 v1(150.851,32.577)
TYPEC0_OTG_D_P: R94.1 U3.AL12 | length 55.7
  Top Layer 1 _Signal w0.131: U3.AL12@149.276,70.778 U3.AL12@149.279,70.778 v1(149.639,70.418) ; v1(151.334,32.577) 151.247,32.489 151.247,30.887 152.724,29.41 161.083,29.41 162.221,28.273 162.221,26.641 162.586,26.277 R94.1@162.586,25.961
  L3_Signals w0.118: v1(149.639,70.418) 149.639,69.975 149.104,69.439 149.104,37.498 151.239,35.363 151.239,32.748 151.334,32.653 v1(151.334,32.577)
TYPEC0_SSRX1_N: R96.1 U3.AP13 | length 54
  Top Layer 1 _Signal w0.131: v1(149.882,67.987) 149.934,68.038 149.934,68.162 149.97,68.198 149.97,68.509 149.961,68.518 149.961,68.797 U3.AP13@149.929,68.828 ; v1(166.026,25.785) 165.851,25.61 165.851,23.938 R96.1@166.233,23.556
  L3_Signals w0.118: v1(149.882,67.987) 149.882,68.063 150.011,68.191 150.011,68.424 150.213,68.626 151.034,68.626 154.078,65.582 154.078,49.643 159.644,44.076 159.644,33.431 159.998,33.077 165.938,27.137 165.938,25.949 166.026,25.861 v1(166.026,25.785)
TYPEC0_SSRX1_P: R97.1 U3.AN13 | length 54.4
  Top Layer 1 _Signal w0.131: U3.AN13@149.929,69.478 149.929,69.436 150.27,69.095 150.27,68.646 150.279,68.637 150.279,68.198 150.315,68.162 150.315,68.038 v1(150.366,67.987) ; R97.1@165.076,23.565 165.542,24.03 v1(165.542,25.785)
  L3_Signals w0.118: v1(150.366,67.987) 150.366,68.063 150.238,68.191 150.238,68.33 150.307,68.399 150.94,68.399 153.851,65.488 153.851,49.549 159.417,43.982 159.417,33.289 159.383,33.255 159.519,33.119 cw(c159.436,33.036) 159.519,32.952 159.436,32.869 ccw(c159.483,32.822) 159.436,32.774 ccw(c159.483,32.822) 159.53,32.774 159.614,32.858 cw(c159.697,32.774) 159.781,32.858 160.301,32.338 165.63,27.009 165.63,25.949 165.542,25.861 v1(165.542,25.785)
TYPEC0_SSTX1_N: C457.1 U3.AN14 | length 47.6
  Top Layer 1 _Signal w0.131: U3.AN14@150.579,69.478 150.579,69.427 150.717,69.29 150.717,69.128 150.92,68.925 150.92,68.53 150.999,68.45 150.999,68.21 152.401,66.809 152.401,66.79 152.601,66.59 v1(152.601,66.253) ; v1(155.716,25.606) 155.677,25.567 155.677,24.585 C457.1@156.081,24.181
  L3_Signals w0.118: v1(152.601,66.253) 152.601,31.325 155.628,28.298 155.628,25.693 v1(155.716,25.606)
TYPEC0_SSTX1_P: C458.1 U3.AP14 | length 46.9
  Top Layer 1 _Signal w0.131: U3.AP14@150.579,68.828 150.615,68.792 150.615,68.677 150.636,68.657 150.636,68.412 150.716,68.333 150.716,68.093 152.117,66.691 v1(152.117,66.253) ; C458.1@154.964,24.228 155.368,24.632 155.368,24.906 155.367,24.907 155.367,25.471 v1(155.232,25.606)
  L3_Signals w0.118: v1(152.117,66.253) 152.117,31.373 155.32,28.17 155.32,25.693 v1(155.232,25.606) 155.309,25.606 v1@155.32,25.617
TYPEC0_USB20_VBUSDET: U3.AM14
TYPEC1_OTG_D_N: R173.1 U3.AL9 | length 47.1
  Top Layer 1 _Signal w0.131: R173.1@139.133,27.242 139.451,27.56 139.451,28.198 v1(139.365,28.284) ; v1(147.028,70.49) 147.035,70.49 147.322,70.778 U3.AL9@147.329,70.778
  L3_Signals w0.118: v1(139.365,28.284) 139.385,28.284 139.453,28.351 139.453,60.599 147.065,68.212 147.065,70.453 v1(147.028,70.49)
TYPEC1_OTG_D_P: R174.1 U3.AK9 | length 48.1
  Top Layer 1 _Signal w0.131: v1(139.849,28.284) 139.76,28.196 139.76,27.543 R174.1@140.079,27.225 ; v1(147.068,71.178) 147.073,71.178 147.324,71.428 U3.AK9@147.329,71.428
  L3_Signals w0.118: v1(139.849,28.284) 139.828,28.284 139.761,28.351 139.761,60.471 147.768,68.478 147.768,70.235 147.17,70.833 147.159,70.833 147.09,70.903 147.09,71.155 v1(147.068,71.178)
UART0_RX: R193.1 U35.3 | length 32.6
  Top Layer 1 _Signal w0.254: U35.3@20.569,112.153 v1(20.569,113.117) ; R193.1@45.634,124.85 45.675,124.809 45.675,122.173 v1(45.703,122.145)
  L3_Signals w0.254: v1(20.569,113.117) 23.726,113.117 29.285,118.677 42.234,118.677 v1(45.703,122.145)
UART0_TX: R191.1 U35.2 | length 35.2
  Top Layer 1 _Signal w0.254: U35.2@20.169,112.153 20.169,112.936 20.158,112.947 20.158,113.778 v1(20.474,114.094) ; v1(48.068,123.799) 48.096,123.827 48.096,124.013 48.587,124.505 R191.1@49.205,124.505
  L3_Signals w0.254: v1(20.474,114.094) 22.038,114.094 27.173,119.229 41.741,119.229 46.312,123.799 v1(48.068,123.799)
UART2_RX_M0_DEBUG: R164.1 U3.R29 | length 70.2
  Top Layer 1 _Signal w0.203: R164.1@210.356,116.258 210.386,116.228 210.386,115.389 v1(210.416,115.359)
  Top Layer 1 _Signal w0.254: v1(160.074,81.416) 160.311,81.178 U3.R29@160.329,81.178
  L3_Signals w0.203: v1(160.074,81.416) 160.678,81.416 161.151,81.888 161.417,81.888 184.974,105.445 208.231,105.445 210.416,107.629 v1(210.416,115.359)
UART2_TX_M0_DEBUG: R165.1 U3.P29 | length 55.8
  Top Layer 1 _Signal w0.203: v1(204.698,106.044) 204.722,106.068 204.722,106.692 R165.1@204.745,106.716
  Top Layer 1 _Signal w0.254: v1(160.08,82.111) 160.08,82.095 160.329,81.846 U3.P29@160.329,81.828
  L3_Signals w0.203: v1(160.08,82.111) 160.133,82.111 160.356,81.888 160.745,81.888 161.274,82.417 161.53,82.417 185.157,106.044 v1(204.698,106.044)
UART3_RX_M2: R170.2 U3.AL27 | length 96
  Top Layer 1 _Signal w0.205: U3.AL27@159.029,70.778 159.029,70.774 159.27,70.533 v1(159.27,70.53) ; R170.2@231.044,19.986 231.83,19.986 231.906,20.062 v1(231.959,20.062)
  L8_Signals w0.205: v1(159.27,70.53) 159.27,68.631 160.827,67.074 160.836,67.074 167.828,60.082 182.521,60.082 218.029,24.574 227.446,24.574 v1(231.959,20.062)
UART3_TX_M2: R171.2 U3.AK27 | length 93.4
  Top Layer 1 _Signal w0.205: U3.AK27@159.029,71.428 159.035,71.428 159.325,71.138 v1(159.331,71.138) ; v1(230.54,25.118) 230.54,25.065 230.65,24.955 R171.2@230.65,23.689
  L8_Signals w0.205: v1(159.331,71.138) 159.733,70.736 159.733,68.794 161.247,67.28 161.388,67.28 168.066,60.602 182.592,60.602 217.963,25.23 223.526,25.23 223.67,25.374 229.232,25.374 229.488,25.118 v1(230.54,25.118)
USB.nRESET: U1.C3
USB.OC_DET: U1.D1
USB_HOST_PWREN_H: U3.AK26 | length 0.3
  Top Layer 1 _Signal w0.132: U3.AK26@158.379,71.428 v1(158.618,71.189)
USB_N: R166.2 U31.1 USB1.2 | length 5.5
  Top Layer 1 _Signal w0.161: USB1.2@204.258,129.303 204.258,128.073 204.014,127.83 204.014,125.889 U31.1@204.621,125.282 204.621,124.902 204.376,124.656 R166.2@204.376,124.235
USB_P: R167.2 U30.1 USB1.3 | length 5.5
  Top Layer 1 _Signal w0.161: R167.2@203.02,124.255 203.02,124.837 202.956,124.902 U30.1@202.956,125.282 203.701,126.027 203.701,127.83 203.458,128.073 USB1.3@203.458,129.303
UV: Q16.3 R208.1 R210.2 U42.7 | length 17.9
  Top Layer 1 _Signal w0.457: v1(27.154,29.979) U42.7@27.154,33.296 ; R208.1@29.659,22.329 29.731,22.256 30.308,22.256 30.507,22.455 30.507,23.504 v1(30.813,23.81) ; 30.507,22.299 32.617,22.299 Q16.3@32.632,22.314 32.664,22.282 34.942,22.282 R210.2@34.974,22.25
  Bottom Layer_Signals w0.457: v1(27.154,29.979) 30.813,26.32 v1(30.813,23.81)
VCC1: C49.1 C50.1 C59.1 C60.1 C68.1 C75.1 C77.1 C161.1 C173.1 C175.1 C179.1 C199.2 C200.2 C449.1 C450.1 C452.1 C485.2 C493.2 C500.2 C501.2 C509.2 C510.2 C552.1 C558.2 D1.1 L17.2 R84.2 R126.1 TP15.1 TP23.1 TP37.1 TP71.1 U5.1 U5.7 U5.21 U5.22 U5.27 U5.28 U5.33 U5.34 U5.43 U5.44 U5.52 U5.53 U5.54 U5.64 U19.5 U22.D1 U22.D2 U22.E1 U22.E2 U23.D1 U23.D2 U23.E1 U23.E2 U24.D1 U24.D2 U24.E1 U24.E2 U25.4 | length 299.9
  Top Layer 1 _Signal w0.089: v1(101.845,56.493) 101.856,56.504 102.332,56.504 v1(102.343,56.515) 102.372,56.515 102.667,56.809 102.689,56.809 v1(102.693,56.806)
  Top Layer 1 _Signal w0.254: TP37.1@75.237,63.671 76.961,63.671 C59.1@77.102,63.813 75.997,64.919 C179.1@75.286,64.919 ; 88.708,56.931 88.829,57.052 89.364,57.052 v1(89.392,57.08) ; v1(90.458,61.555) 90.448,61.565 89.904,61.565 v1(89.895,61.574) 89.88,61.56 89.327,61.56 v1(89.312,61.546) 89.317,61.541 89.317,60.835 v1(89.322,60.83) 89.327,60.835 89.928,60.835 v1(89.933,60.84) 89.937,60.835 90.51,60.835 v1(90.515,60.83) 90.554,60.83 90.769,60.615 U5.34@91.399,60.615 ; v1(91.403,52.919) 91.43,52.946 91.954,52.946 v1(91.981,52.973) ; v1@91.451,52.967 91.431,52.987 91.431,53.157 U5.53@91.707,53.432 ; v1(92.574,62.676) 92.602,62.648 92.602,62.574 v1(92.947,62.229) 92.974,62.229 93.298,61.904 v1(93.325,61.904) 93.33,61.904 93.818,61.416 93.818,60.646 U5.27@93.849,60.615 ; C60.1@94.824,42.708 94.824,43.919 v1(94.796,43.946) 94.828,43.978 v1@94.828,44.053 ; U5.64@95.599,53.725 95.599,51.55 95.68,51.469 v1(95.68,51.43) 95.68,51.419 95.975,51.124 v1(95.975,51.112) ; v1(95.792,63.285) 95.799,63.278 95.799,62.678 v1(95.807,62.671) 95.792,62.656 95.792,62.184 v1(95.777,62.17) 95.777,61.723 95.949,61.551 U5.21@95.949,60.615 ; v1(96.83,43.946) 96.83,42.807 C161.1@96.899,42.738 ; U5.1@97.644,54.37 101.214,54.37 101.62,54.776 v1(101.63,54.776) 101.643,54.764 102.105,54.764 v1(102.117,54.751) 102.13,54.764 v1@102.605,54.764 ; U5.7@97.644,56.47 102.357,56.47 v1(102.693,56.806) ; C173.1@99.196,42.743 99.4,42.948 v1(99.4,43.599) ; C77.1@101.325,42.721 101.882,43.278 102.047,43.278 v1(102.075,43.306) ; v1(102.592,54.34) 102.605,54.352 v1@102.605,54.764 ; v1(102.617,54.776) v1@102.605,54.764 ; C50.1@106.201,52.463 106.201,52.663 106.887,53.349 108.263,53.349 108.274,53.339 108.837,53.339 109.001,53.175 TP15.1@110.027,53.175 ; TP23.1@179.604,38.396 180.431,39.224 183.307,39.224 ; v1(189.898,28.533) v1(189.898,29.061) 189.938,29.061 189.979,29.02 191.357,29.02 U22.D1@191.399,29.061 U22.D2@191.799,29.061
  Top Layer 1 _Signal w0.381: U19.5@53.538,60.183 53.603,60.248 53.603,60.538 53.983,60.917 54.086,60.917 v1(54.09,60.921) ; R84.2@54.398,64.597 54.4,64.6 54.977,64.6 55.264,64.6 v1(55.266,64.602)
  Top Layer 1 _Signal w0.635: v1(208.266,19.826) R126.1@210.42,19.826 211.92,19.826 212.131,20.037 U25.4@212.296,20.037
  Top Layer 1 _Signal w0.762: TP71.1@176.712,8.592 176.712,8.431 176.934,8.21 ; C501.2@178.276,6.627 C501.2@178.276,6.627 179.345,6.626 180.05,5.922 180.05,5.224 v1(180.024,5.198) ; v1(180.007,3.959) v1(180.007,4.527)
  Top Layer 1 _Signal w1.27: 54.977,64.6 55.005,64.572 C449.1@58.191,64.572 ; C200.2@58.368,68.962 58.624,69.218 58.624,69.81 59.045,70.231 63.626,70.231 69.026,64.831 75.237,64.831 75.237,64.724 TP37.1@75.237,63.671 ; v1(175.866,9.142) 176.798,8.21 ; 176.934,8.21 v1(177.418,8.21) 177.418,8.141 v1(177.916,7.643) 177.916,7.227 C501.2@178.261,6.882 ; v1(178.886,44.267) v1@181.789,44.267 ; v1(181.666,44.387) 182.268,44.387 183.513,43.143 C510.2@183.513,42.242
  L8_Signals w0.762: v1(91.981,52.973) 91.403,52.973 v1(90.912,52.974) 89.908,52.973 88.809,51.874 88.809,47.081 88.663,46.935 88.663,45.159 88.38,44.876 88.38,44.325 88.663,44.042 88.663,41.491 91.552,38.602 91.552,37.217 105.404,23.364 105.955,23.364 107.214,24.624 120.36,24.624 124.243,20.74 164.268,20.74 v1(175.866,9.142) 176.798,8.21 v1(177.418,8.21) 177.418,8.141 v1(177.916,7.643) 177.916,7.438 178.067,7.286
  Bottom Layer_Signals w0.254: C175.1@88.679,56.976 88.783,57.08 v1(89.392,57.08) v1(90.001,57.08) ; v1(90.912,52.974) v1@90.927,52.989 ; v1(95.68,51.43) 95.68,51.419 95.975,51.124 v1(95.975,51.112)
  Bottom Layer_Signals w0.381: v1(54.09,60.921) 54.09,61.775 54.728,62.413 54.728,64.064 v1(55.266,64.602)
  Bottom Layer_Signals w0.508: v1(95.68,51.43) 99.026,54.776 v1(101.63,54.776) v1(102.617,54.776)
  Bottom Layer_Signals w1.27: v1(178.886,44.267) 181.666,44.267 182.928,43.005 186.863,43.005 187.401,42.467 187.401,40.456 189.898,37.96 189.898,32.156 ; v1(180.007,4.527) 180.007,7.803 186.023,13.819 186.023,17.933 189.86,21.769 189.86,22.801 191.501,24.442 ; v1(189.898,28.533) v1(189.898,29.061) 189.898,32.156 ; v1(208.266,19.826) 203.65,24.442 191.501,24.442 ; 189.898,32.156 191.934,30.12 191.934,24.875 191.501,24.442
  other v1: 182.208,43.946 179.92,44.357 180.672,44.397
